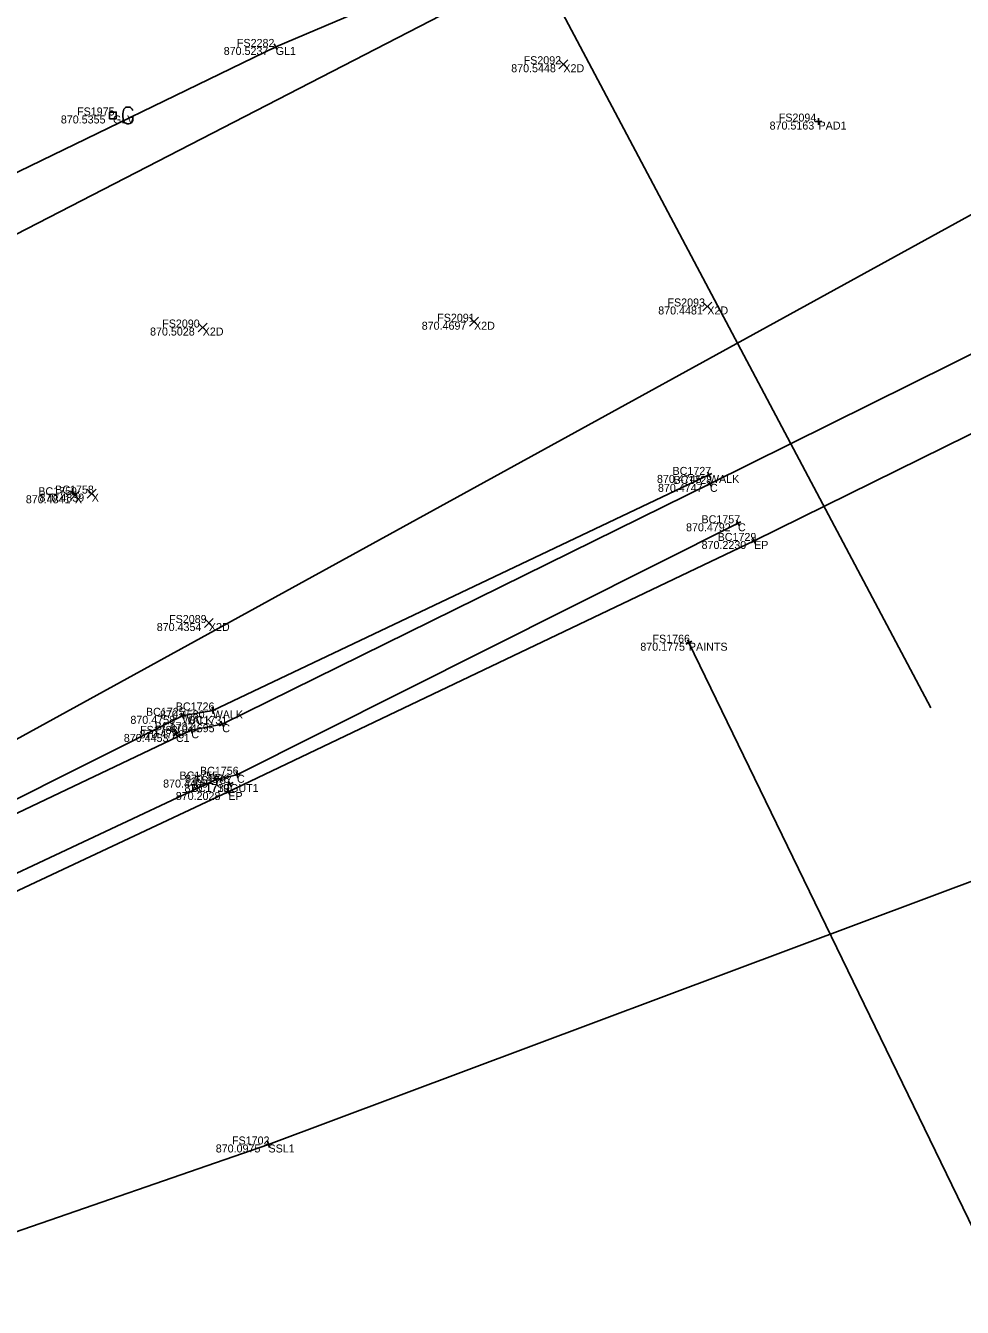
# Model space of a CAD drawing. Extents: x 1479425 to 1480294, y 379351 to 380102.
# Drawn here: x 1479677.28 to 1479684.31, y 379943.62 to 379953.22 of the extents above; entities that cross this region are included whole.
import ezdxf

# ---------------------------------------------------------------- set-up
doc = ezdxf.new("R2010")
doc.units = 0
for name, color, linetype in [('Default', 7, 'Continuous'), ('PM_X_Stop_Line', 7, 'Continuous'), ('PV_X_Curb', 7, 'Continuous'), ('PV_X_Walk', 7, 'Continuous'), ('SV_X_Random_Point', 7, 'Continuous'), ('SV_X_Shot_Marker', 7, 'Continuous'), ('SV_X_Text_Comment', 7, 'Continuous'), ('SV_X_Text_Elevation', 7, 'Continuous'), ('SV_X_Text_Name', 7, 'Continuous'), ('UT_X_Gas', 7, 'Continuous'), ('UT_X_Gas_Cells', 7, 'Continuous'), ('UT_X_Sanitary_Line', 7, 'Continuous'), ('UT_X_Telecom', 7, 'Continuous')]:
    doc.layers.add(name, color=color, linetype=linetype)

msp = doc.modelspace()

# ---------------------------------------------------------------- linework, layer by layer
at = {"layer": 'Default'}
msp.add_line((1479680.1883, 379955.4308), (1479684.0693, 379948.11), dxfattribs=at)
at = {"layer": 'PM_X_Stop_Line'}
msp.add_lwpolyline([(1479682.255, 379948.5987), (1479686.899, 379939.0296)], dxfattribs=at)
at = {"layer": 'PV_X_Curb'}
for points in [[(1479791.59, 380003.4635), (1479772.982, 379994.3805), (1479762.438, 379989.2296), (1479737.891, 379977.2252), (1479720.638, 379968.6113), (1479698.71, 379957.883), (1479682.4127, 379949.7895), (1479678.7563, 379947.9876), (1479678.5248, 379947.9422), (1479675.4654, 379946.4876), (1479673.9091, 379945.7738), (1479671.0561, 379944.4897), (1479670.8808, 379944.4504), (1479668.8369, 379943.6961), (1479667.0164, 379943.0245), (1479664.845, 379942.3912), (1479664.6467, 379942.3345), (1479664.117, 379942.1619), (1479661.876, 379941.9004), (1479659.999, 379941.9714), (1479653.935, 379943.2676), (1479649.182, 379945.5268), (1479644.261, 379948.8889)], [(1479791.848, 380002.9887), (1479773.254, 379993.8725), (1479762.766, 379988.7719), (1479738.122, 379976.6433), (1479720.845, 379968.2141), (1479698.694, 379957.2389), (1479682.744, 379949.3616), (1479678.8019, 379947.4796), (1479675.6873, 379946.0213), (1479671.3231, 379944.0259), (1479668.9901, 379943.1057), (1479665.6381, 379942.0412), (1479664.1435, 379941.5823), (1479662.026, 379941.3965), (1479659.994, 379941.5118), (1479654.023, 379942.7671), (1479648.758, 379945.1011), (1479643.81, 379948.5526)], [(1479664.2039, 379941.7379), (1479664.7376, 379941.8534), (1479664.9193, 379941.9176), (1479667.0854, 379942.5936), (1479669.0389, 379943.2625), (1479671.0702, 379944.0635), (1479673.8108, 379945.3222), (1479675.8363, 379946.2235), (1479678.7099, 379947.5729), (1479678.8669, 379947.6085), (1479682.6232, 379949.494)]]:
    msp.add_lwpolyline(points, dxfattribs=at)
at = {"layer": 'PV_X_Walk'}
for points in [[(1479680.531, 379953.5783), (1479680.5594, 379953.3846), (1479676.9646, 379951.5344), (1479676.7347, 379951.4915), (1479675.3165, 379950.8518), (1479673.7719, 379950.1464), (1479670.8196, 379948.7758), (1479669.4595, 379948.1937), (1479669.388, 379947.9546), (1479669.0403, 379947.6975), (1479668.7338, 379947.7557), (1479668.5535, 379947.8945), (1479667.7241, 379947.5602), (1479667.7995, 379947.6709), (1479667.4767, 379949.4768), (1479667.1248, 379951.2892), (1479667.1368, 379951.4103), (1479666.7498, 379953.3122), (1479666.5215, 379955.0904), (1479666.4393, 379955.1162), (1479666.0253, 379957.6131), (1479665.7712, 379958.9526), (1479665.7102, 379959.0342), (1479665.0761, 379962.8267)], [(1479668.8228, 379943.7878), (1479670.7322, 379944.5055), (1479672.2751, 379945.1262), (1479673.8874, 379945.9158), (1479675.4876, 379946.6168), (1479677.0508, 379947.3467), (1479678.4574, 379948.0505), (1479678.6848, 379948.0907), (1479682.4053, 379949.8566)]]:
    msp.add_lwpolyline(points, dxfattribs=at)
at = {"layer": 'SV_X_Random_Point'}
for p, q in [((1479681.2807, 379952.9021), (1479681.3473, 379952.9689)), ((1479681.2807, 379952.9689), (1479681.3473, 379952.9021)), ((1479682.3597, 379951.0861), (1479682.4263, 379951.1529)), ((1479682.3597, 379951.1529), (1479682.4263, 379951.0861)), ((1479680.6107, 379950.9716), (1479680.6773, 379951.0384)), ((1479680.6107, 379951.0384), (1479680.6773, 379950.9716)), ((1479678.5767, 379950.9281), (1479678.6433, 379950.9949)), ((1479678.5767, 379950.9949), (1479678.6433, 379950.9281)), ((1479677.6185, 379949.6707), (1479677.6851, 379949.7375)), ((1479677.6185, 379949.7375), (1479677.6851, 379949.6707)), ((1479677.7446, 379949.6831), (1479677.8112, 379949.7499)), ((1479677.7446, 379949.7499), (1479677.8112, 379949.6831)), ((1479678.6227, 379948.7128), (1479678.6893, 379948.7796)), ((1479678.6227, 379948.7796), (1479678.6893, 379948.7128))]:
    msp.add_line(p, q, dxfattribs=at)
at = {"layer": 'SV_X_Shot_Marker'}
for p, q in [((1479679.1345, 379953.0542), (1479679.1795, 379953.076)), ((1479679.1461, 379953.0876), (1479679.1679, 379953.0426)), ((1479679.157, 379953.0651), (1479679.157, 379953.0651)), ((1479683.202, 379952.5056), (1479683.252, 379952.5056)), ((1479683.227, 379952.5306), (1479683.227, 379952.4806)), ((1479683.227, 379952.5056), (1479683.227, 379952.5056)), ((1479682.3827, 379949.8459), (1479682.4279, 379949.8673)), ((1479682.3946, 379949.8792), (1479682.416, 379949.834)), ((1479682.4053, 379949.8566), (1479682.4053, 379949.8566)), ((1479682.4351, 379949.8006), (1479682.3903, 379949.7784)), ((1479682.4238, 379949.7671), (1479682.4016, 379949.8119)), ((1479682.4127, 379949.7895), (1479682.4127, 379949.7895)), ((1479682.6009, 379949.4828), (1479682.6455, 379949.5052)), ((1479682.612, 379949.5164), (1479682.6344, 379949.4717)), ((1479682.6232, 379949.494), (1479682.6232, 379949.494)), ((1479682.7664, 379949.3727), (1479682.7216, 379949.3505)), ((1479682.7551, 379949.3392), (1479682.7329, 379949.384)), ((1479682.744, 379949.3616), (1479682.744, 379949.3616)), ((1479682.2775, 379948.6096), (1479682.2325, 379948.5878)), ((1479682.2441, 379948.6212), (1479682.2659, 379948.5762)), ((1479682.255, 379948.5987), (1479682.255, 379948.5987)), ((1479678.435, 379948.0393), (1479678.4798, 379948.0617)), ((1479678.4462, 379948.0729), (1479678.4686, 379948.0282)), ((1479678.4574, 379948.0505), (1479678.4574, 379948.0505)), ((1479678.6602, 379948.0864), (1479678.7094, 379948.0951)), ((1479678.6804, 379948.1153), (1479678.6891, 379948.0661)), ((1479678.6848, 379948.0907), (1479678.6848, 379948.0907)), ((1479678.4196, 379947.8922), (1479678.3984, 379947.9375)), ((1479678.5493, 379947.947), (1479678.5003, 379947.9374)), ((1479678.5296, 379947.9177), (1479678.52, 379947.9668)), ((1479678.5248, 379947.9422), (1479678.5248, 379947.9422)), ((1479678.7787, 379947.9987), (1479678.7339, 379947.9766)), ((1479678.7673, 379947.9652), (1479678.7452, 379948.01)), ((1479678.7563, 379947.9876), (1479678.7563, 379947.9876)), ((1479678.4316, 379947.9254), (1479678.3864, 379947.9042)), ((1479678.409, 379947.9148), (1479678.409, 379947.9148)), ((1479678.6873, 379947.5623), (1479678.7325, 379947.5835)), ((1479678.6993, 379947.5955), (1479678.7205, 379947.5503)), ((1479678.7099, 379947.5729), (1479678.7099, 379947.5729)), ((1479678.8375, 379947.5502), (1479678.7925, 379947.5283)), ((1479678.826, 379947.5168), (1479678.804, 379947.5617)), ((1479678.8425, 379947.603), (1479678.8913, 379947.614)), ((1479678.8614, 379947.6329), (1479678.8724, 379947.5841)), ((1479678.8669, 379947.6085), (1479678.8669, 379947.6085)), ((1479678.8245, 379947.4904), (1479678.7793, 379947.4688)), ((1479678.8127, 379947.4571), (1479678.7911, 379947.5022)), ((1479678.8019, 379947.4796), (1479678.8019, 379947.4796)), ((1479678.815, 379947.5392), (1479678.815, 379947.5392)), ((1479679.0948, 379944.8606), (1479679.1112, 379944.8134)), ((1479679.0794, 379944.8289), (1479679.1266, 379944.8452)), ((1479679.103, 379944.837), (1479679.103, 379944.837))]:
    msp.add_line(p, q, dxfattribs=at)
at = {"layer": 'UT_X_Gas'}
msp.add_lwpolyline([(1479646.785, 379955.4381), (1479652.981, 379949.4327), (1479657.465, 379945.9636), (1479660.591, 379945.0242), (1479670.935, 379949.0796), (1479679.157, 379953.0651), (1479685.442, 379955.7424), (1479689.462, 379958.1268), (1479696.956, 379963.0127), (1479705.088, 379967.4878), (1479713.465, 379971.2262), (1479723.024, 379975.6759), (1479732.065, 379980.116), (1479742.535, 379985.0181), (1479753.798, 379990.643), (1479767.065, 379997.4563), (1479775.982, 380001.7332), (1479789.966, 380007.7888)], dxfattribs=at)
at = {"layer": 'UT_X_Gas_Cells'}
for points in [[(1479677.912, 379952.5265), (1479677.962, 379952.5265), (1479677.962, 379952.5765), (1479677.912, 379952.5765), (1479677.912, 379952.5265)], [(1479678.0852, 379952.5897), (1479678.0842, 379952.5947), (1479678.0812, 379952.5996), (1479678.0763, 379952.6045), (1479678.0694, 379952.6104), (1479678.0645, 379952.6124), (1479678.0606, 379952.6134), (1479678.0547, 379952.6144), (1479678.0428, 379952.6144), (1479678.0379, 379952.6134), (1479678.035, 379952.6124), (1479678.031, 379952.6104), (1479678.0232, 379952.6045), (1479678.0182, 379952.5976), (1479678.0153, 379952.5897), (1479678.0133, 379952.5789), (1479678.0113, 379952.5632), (1479678.0113, 379952.5425), (1479678.0123, 379952.5258), (1479678.0163, 379952.513), (1479678.0222, 379952.5012), (1479678.0271, 379952.4972), (1479678.033, 379952.4933), (1479678.0438, 379952.4894), (1479678.0547, 379952.4894), (1479678.0655, 379952.4913), (1479678.0694, 379952.4933), (1479678.0734, 379952.4953), (1479678.0773, 379952.4992), (1479678.0812, 379952.5051), (1479678.0852, 379952.514), (1479678.0852, 379952.5386), (1479678.0645, 379952.5386)]]:
    msp.add_lwpolyline(points, dxfattribs=at)
at = {"layer": 'UT_X_Sanitary_Line'}
msp.add_lwpolyline([(1479514.622, 379866.8703), (1479542.109, 379880.1949), (1479565.169, 379891.7253), (1479588.442, 379902.5771), (1479600.276, 379909.0452), (1479620.421, 379921.0629), (1479621.963, 379921.4851), (1479624.647, 379923.4166), (1479645.234, 379932.5118), (1479652.585, 379935.6159), (1479664.157, 379939.675), (1479679.103, 379944.837), (1479710.112, 379956.4476), (1479736.037, 379968.2328), (1479798.147, 379991.1675), (1479820.4, 379999.933), (1479823.042, 380000.22)], dxfattribs=at)
at = {"layer": 'UT_X_Telecom'}
msp.add_lwpolyline([(1479654.736, 379936.5803), (1479659.767, 379940.788), (1479670.95, 379944.4342), (1479693.183, 379956.6524)], dxfattribs=at)

# ---------------------------------------------------------------- texts
at = {"layer": 'SV_X_Text_Comment'}
for s, p in [('GL1', (1479679.157, 379953.0051)), ('X2D', (1479681.314, 379952.8755)), ('GLV', (1479677.937, 379952.4915)), ('PAD1', (1479683.227, 379952.4456)), ('X2D', (1479682.393, 379951.0595)), ('X2D', (1479680.644, 379950.945)), ('X2D', (1479678.61, 379950.9015)), ('WALK', (1479682.4053, 379949.7966)), ('C', (1479682.4127, 379949.7295)), ('X', (1479677.6518, 379949.6441)), ('X', (1479677.7779, 379949.6565)), ('C', (1479682.6232, 379949.434)), ('EP', (1479682.744, 379949.3016)), ('X2D', (1479678.656, 379948.6862)), ('PAINTS', (1479682.255, 379948.5387)), ('WALK', (1479678.4574, 379947.9905)), ('WALK', (1479678.6848, 379948.0307)), ('C', (1479678.5248, 379947.8822)), ('C', (1479678.7563, 379947.9276)), ('C1', (1479678.409, 379947.8548)), ('C', (1479678.7099, 379947.5129)), ('C', (1479678.8669, 379947.5485)), ('EP', (1479678.8019, 379947.4196)), ('GUT1', (1479678.815, 379947.4792)), ('SSL1', (1479679.103, 379944.777))]:
    msp.add_text(s, height=0.06, dxfattribs=at).set_placement(p)
at = {"layer": 'SV_X_Text_Elevation'}
for s, p in [('870.5237', (1479678.7673, 379953.0051)), ('870.5448', (1479680.9228, 379952.8755)), ('870.5355', (1479677.5463, 379952.4915)), ('870.5163', (1479682.86, 379952.4456)), ('870.4481', (1479682.0249, 379951.0595)), ('870.4697', (1479680.2519, 379950.945)), ('870.5028', (1479678.2151, 379950.9015)), ('870.4745', (1479682.0156, 379949.7966)), ('870.4747', (1479682.023, 379949.7295)), ('870.4841', (1479677.2837, 379949.6441)), ('870.4839', (1479677.3863, 379949.6565)), ('870.4792', (1479682.2335, 379949.434)), ('870.2230', (1479682.35, 379949.3016)), ('870.4354', (1479678.2653, 379948.6862)), ('870.1775', (1479681.8908, 379948.5387)), ('870.4758', (1479678.0677, 379947.9905)), ('870.4580', (1479678.2894, 379948.0307)), ('870.4728', (1479678.136, 379947.8822)), ('870.4695', (1479678.3642, 379947.9276)), ('870.4453', (1479678.0183, 379947.8548)), ('870.4408', (1479678.3131, 379947.5129)), ('870.4578', (1479678.4772, 379947.5485)), ('870.2028', (1479678.4079, 379947.4196)), ('870.1719', (1479678.473, 379947.4792)), ('870.0975', (1479678.7076, 379944.777))]:
    msp.add_text(s, height=0.06, dxfattribs=at).set_placement(p)
at = {"layer": 'SV_X_Text_Name'}
for s, p in [('FS2282', (1479678.8665, 379953.0651)), ('FS2092', (1479681.0159, 379952.9355)), ('FS1975', (1479677.6678, 379952.5515)), ('FS2094', (1479682.9289, 379952.5056)), ('FS2093', (1479682.0944, 379951.1195)), ('FS2090', (1479678.3062, 379950.9615)), ('FS2091', (1479680.368, 379951.005)), ('BC1727', (1479682.1323, 379949.8566)), ('BC1728', (1479682.1392, 379949.7895)), ('BC1759', (1479677.3774, 379949.7041)), ('BC1758', (1479677.5035, 379949.7165)), ('BC1757', (1479682.3492, 379949.494)), ('BC1729', (1479682.4705, 379949.3616)), ('FS2089', (1479678.3579, 379948.7462)), ('FS1766', (1479681.982, 379948.5987)), ('BC1726', (1479678.408, 379948.0907)), ('BC1725', (1479678.1844, 379948.0505)), ('BC1731', (1479678.5039, 379947.9876)), ('FS1788', (1479678.1402, 379947.9148)), ('BC1732', (1479678.2504, 379947.9422)), ('BC1756', (1479678.5892, 379947.6085)), ('BC1755', (1479678.4359, 379947.5729)), ('FS1787', (1479678.5467, 379947.5392)), ('BC1730', (1479678.5218, 379947.4796)), ('FS1702', (1479678.8295, 379944.837))]:
    msp.add_text(s, height=0.06, dxfattribs=at).set_placement(p)

doc.saveas('drawing.dxf')
